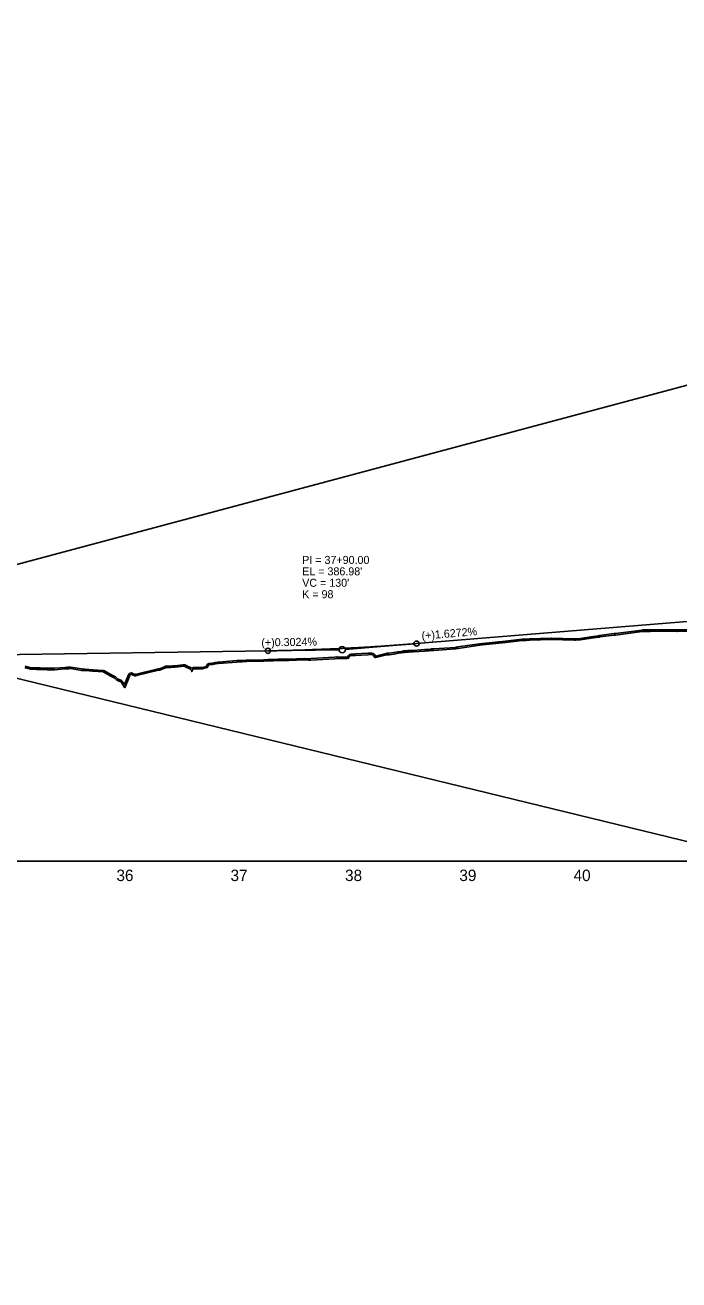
# Model space of a CAD drawing. Extents: x 1625686 to 1640492, y 1161393 to 1175642.
# Drawn here: x 1638424 to 1638996, y 1174544 to 1175642 of the extents above; entities that cross this region are included whole.
import ezdxf

# ---------------------------------------------------------------- set-up
doc = ezdxf.new("R2010")
doc.units = 0
for name, color, linetype in [('Exist Profile Cell', 7, 'Continuous'), ('Exist Vertical Profile Horizontal Axis Label Major', 7, 'Continuous'), ('Prop Vertical Profile Curve Label', 7, 'Continuous'), ('Prop Vertical Profile Grade', 7, 'Continuous'), ('Prop Vertical Profile Grade Label', 7, 'Continuous'), ('Prop VPI Label', 7, 'Continuous'), ('Scratch_Level_1', 7, 'Continuous'), ('Scratch_Level_3', 7, 'Continuous')]:
    doc.layers.add(name, color=color, linetype=linetype)

msp = doc.modelspace()

# ---------------------------------------------------------------- linework, layer by layer
at = {"layer": 'Exist Profile Cell'}
msp.add_line((1635911.8, 1174910.8), (1640378.1, 1174910.8), dxfattribs=at)
at = {"layer": 'Prop Vertical Profile Curve Label'}
for centre in [(1638636.8, 1175094.7), (1638766.8, 1175101)]:
    msp.add_circle(centre, 2.25, dxfattribs=at)
at = {"layer": 'Prop Vertical Profile Grade'}
for p, q in [((1638766.8, 1175101), (1639351.8, 1175148.6)), ((1638011.8, 1175085.3), (1638636.8, 1175094.7))]:
    msp.add_line(p, q, dxfattribs=at)
msp.add_spline([(1638636.8, 1175094.7), (1638639.4, 1175094.7), (1638642, 1175094.8), (1638644.6, 1175094.8), (1638647.2, 1175094.9), (1638649.8, 1175094.9), (1638652.4, 1175095), (1638655, 1175095.1), (1638657.6, 1175095.1), (1638660.2, 1175095.2), (1638662.8, 1175095.3), (1638665.4, 1175095.3), (1638668, 1175095.4), (1638670.6, 1175095.5), (1638673.2, 1175095.6), (1638675.8, 1175095.7), (1638678.4, 1175095.8), (1638681, 1175095.9), (1638683.6, 1175096), (1638686.2, 1175096.1), (1638688.8, 1175096.2), (1638691.4, 1175096.3), (1638694, 1175096.4), (1638696.6, 1175096.5), (1638699.2, 1175096.6), (1638701.8, 1175096.8), (1638704.4, 1175096.9), (1638707, 1175097), (1638709.6, 1175097.2), (1638712.2, 1175097.3), (1638714.8, 1175097.4), (1638717.4, 1175097.6), (1638720, 1175097.7), (1638722.6, 1175097.9), (1638725.2, 1175098), (1638727.8, 1175098.2), (1638730.4, 1175098.4), (1638733, 1175098.5), (1638735.6, 1175098.7), (1638738.2, 1175098.9), (1638740.8, 1175099), (1638743.4, 1175099.2), (1638746, 1175099.4), (1638748.6, 1175099.6), (1638751.2, 1175099.8), (1638753.8, 1175100), (1638756.4, 1175100.2), (1638759, 1175100.4), (1638761.6, 1175100.6), (1638764.2, 1175100.8), (1638766.8, 1175101)], degree=3, dxfattribs=at)
at = {"layer": 'Prop VPI Label'}
for p, q in [((1638636.8, 1175094.7), (1638699, 1175095.6)), ((1638766.8, 1175101), (1638704.5, 1175095.9))]:
    msp.add_line(p, q, dxfattribs=at)
msp.add_circle((1638701.8, 1175095.7), 2.75, dxfattribs=at)
at = {"layer": 'Scratch_Level_1'}
for p, q in [((1638866, 1175105.3), (1638884.6, 1175105.8)), ((1638939.5, 1175109.7), (1638940.2, 1175109.7)), ((1638939.7, 1175108.4), (1638940.3, 1175108.5)), ((1638964.4, 1175112.9), (1638965, 1175112.9)), ((1638964.4, 1175111.6), (1638965, 1175111.6)), ((1638965.1, 1175112.9), (1638970.2, 1175112.9)), ((1638965.1, 1175111.6), (1638970.2, 1175111.6)), ((1638995.4, 1175113.1), (1638996.3, 1175113.1)), ((1638995.5, 1175111.9), (1638996.3, 1175111.9)), ((1638754.8, 1175094.4), (1638755.8, 1175094.6)), ((1638756, 1175094.6), (1638757.9, 1175094.7)), ((1638759.7, 1175094.9), (1638761.7, 1175095)), ((1638802.9, 1175098.1), (1638821.9, 1175100.9)), ((1638803.1, 1175096.8), (1638822.1, 1175099.7)), ((1638821.9, 1175100.9), (1638824.5, 1175101.2)), ((1638822.1, 1175099.7), (1638824.6, 1175100)), ((1638836, 1175102.3), (1638838.8, 1175102.6)), ((1638836.1, 1175101), (1638838.9, 1175101.3)), ((1638866, 1175104.1), (1638884.7, 1175104.5)), ((1638590.7, 1175084.5), (1638593.4, 1175084.9)), ((1638590.9, 1175083.3), (1638593.6, 1175083.7)), ((1638593.6, 1175084.9), (1638609.5, 1175086.1)), ((1638593.7, 1175083.7), (1638609.6, 1175084.8)), ((1638609.5, 1175086.1), (1638612.8, 1175086.3)), ((1638609.6, 1175084.8), (1638612.8, 1175085)), ((1638724.2, 1175092.5), (1638727.8, 1175092.6)), ((1638724.3, 1175091.3), (1638727.8, 1175091.4)), ((1638755, 1175093.2), (1638756, 1175093.3)), ((1638756.1, 1175093.3), (1638758, 1175093.5)), ((1638759.7, 1175093.6), (1638761.7, 1175093.7)), ((1638424.2, 1175080), (1638424.8, 1175079.8)), ((1638424.4, 1175081.2), (1638425.1, 1175081.1)), ((1638424.9, 1175079.8), (1638426.1, 1175079.5)), ((1638425.1, 1175081), (1638426.4, 1175080.7)), ((1638437.3, 1175079.7), (1638438, 1175079.6)), ((1638437.3, 1175078.4), (1638438, 1175078.4)), ((1638450.2, 1175079.5), (1638459, 1175080.1)), ((1638450.3, 1175078.2), (1638459.1, 1175078.8)), ((1638462.4, 1175080.3), (1638463.6, 1175080.4)), ((1638462.5, 1175079.1), (1638463.7, 1175079.2)), ((1638476.9, 1175077.4), (1638483.5, 1175076.9)), ((1638477, 1175078.6), (1638483.6, 1175078.2)), ((1638483.5, 1175076.9), (1638492.7, 1175076.2)), ((1638483.6, 1175078.2), (1638492.8, 1175077.4)), ((1638547.7, 1175081.2), (1638548.1, 1175081.3)), ((1638547.7, 1175080), (1638548.2, 1175080)), ((1638560.8, 1175082.2), (1638562.5, 1175082.4)), ((1638560.9, 1175081), (1638562.6, 1175081.2)), ((1638562.6, 1175082.4), (1638563.5, 1175082.4)), ((1638562.7, 1175081.2), (1638563.5, 1175081.2)), ((1638569.6, 1175078), (1638570.1, 1175077))]:
    msp.add_line(p, q, dxfattribs=at)
for points in [[(1638859.5, 1175104.8), (1638862.5, 1175105), (1638865.8, 1175105.3)], [(1638884.7, 1175104.5), (1638904.7, 1175103.9), (1638905.8, 1175103.9), (1638910.3, 1175104.2), (1638919.6, 1175105.7)], [(1638884.8, 1175105.8), (1638904.7, 1175105.1), (1638905.7, 1175105.1), (1638910.2, 1175105.4), (1638919.3, 1175107)], [(1638919.4, 1175107), (1638925.7, 1175107.8), (1638926.2, 1175107.9)], [(1638919.6, 1175105.7), (1638925.9, 1175106.6), (1638926.5, 1175106.7)], [(1638926.4, 1175107.9), (1638927, 1175108), (1638939.4, 1175109.7)], [(1638926.5, 1175106.7), (1638927.1, 1175106.8), (1638939.6, 1175108.4)], [(1638940.3, 1175109.7), (1638940.8, 1175109.8), (1638964.1, 1175112.8)], [(1638940.3, 1175108.5), (1638940.9, 1175108.5), (1638964.3, 1175111.6)], [(1638970.2, 1175112.9), (1638970.6, 1175112.9), (1638971.1, 1175113)], [(1638970.2, 1175111.6), (1638970.7, 1175111.6), (1638971.3, 1175111.7)], [(1638971.5, 1175113), (1638994.5, 1175113), (1638995.2, 1175113.1)], [(1638971.5, 1175111.8), (1638994.6, 1175111.7), (1638995.3, 1175111.8)], [(1638996.3, 1175113.1), (1639007, 1175113.2), (1639009.1, 1175113.3), (1639023.6, 1175114.5), (1639029.2, 1175115)], [(1638996.3, 1175111.9), (1639007, 1175111.9), (1639009.2, 1175112), (1639023.8, 1175113.2), (1639029.4, 1175113.8)], [(1638750.7, 1175093.9), (1638753.3, 1175094.2), (1638753.5, 1175094.2), (1638754.8, 1175094.4)], [(1638758, 1175094.8), (1638758.6, 1175094.8), (1638759.6, 1175094.9)], [(1638761.8, 1175095), (1638764.2, 1175095), (1638774, 1175095.7)], [(1638761.8, 1175093.7), (1638764.3, 1175093.8), (1638774.1, 1175094.5)], [(1638774, 1175095.7), (1638777.4, 1175095.9), (1638779.3, 1175096.2)], [(1638774.1, 1175094.5), (1638777.5, 1175094.7), (1638779.5, 1175095)], [(1638779.6, 1175096.3), (1638781.8, 1175096.4), (1638800.8, 1175097.7), (1638801.7, 1175097.9), (1638802.9, 1175098)], [(1638779.7, 1175095), (1638781.9, 1175095.1), (1638800.9, 1175096.5), (1638801.9, 1175096.6), (1638803.1, 1175096.8)], [(1638824.7, 1175101.2), (1638827.3, 1175101.3), (1638835.9, 1175102.3)], [(1638824.7, 1175100), (1638827.4, 1175100.1), (1638836.1, 1175101)], [(1638838.8, 1175102.6), (1638841.9, 1175102.9), (1638859.3, 1175104.8)], [(1638838.9, 1175101.3), (1638842, 1175101.6), (1638859.5, 1175103.6)], [(1638859.5, 1175103.6), (1638862.6, 1175103.7), (1638865.9, 1175104.1)], [(1638585.2, 1175083.5), (1638588.2, 1175084), (1638590.6, 1175084.5)], [(1638612.9, 1175086.3), (1638614.3, 1175086.3), (1638617.9, 1175086.4)], [(1638612.9, 1175085), (1638614.4, 1175085.1), (1638618, 1175085.2)], [(1638618, 1175086.4), (1638633, 1175086.7), (1638636.9, 1175087.2)], [(1638618, 1175085.2), (1638633.1, 1175085.5), (1638637, 1175085.9)], [(1638637.1, 1175087.2), (1638641.5, 1175087.2), (1638645.4, 1175087.4)], [(1638637.1, 1175085.9), (1638641.5, 1175086), (1638645.4, 1175086.1)], [(1638645.5, 1175087.4), (1638650, 1175087.3), (1638655.1, 1175087.5), (1638668.4, 1175087.9)], [(1638645.5, 1175086.1), (1638650, 1175086.1), (1638655.2, 1175086.2), (1638668.4, 1175086.7)], [(1638668.5, 1175086.7), (1638672, 1175086.5), (1638672.9, 1175086.6)], [(1638668.6, 1175087.9), (1638672, 1175087.8), (1638672.9, 1175087.8)], [(1638672.9, 1175087.8), (1638674.3, 1175087.9), (1638695.1, 1175089.1), (1638696.8, 1175089.3)], [(1638673, 1175086.6), (1638674.4, 1175086.6), (1638695.2, 1175087.8), (1638697, 1175088)], [(1638697.2, 1175089.3), (1638699.1, 1175089.2), (1638705.9, 1175089.2), (1638706.5, 1175089.4), (1638707.2, 1175090.6)], [(1638697.2, 1175088), (1638699.1, 1175088), (1638706, 1175088), (1638707.3, 1175088.2), (1638708.3, 1175089.9)], [(1638709.2, 1175091.8), (1638713.3, 1175092), (1638724.2, 1175092.5)], [(1638709.3, 1175090.5), (1638713.3, 1175090.7), (1638724.2, 1175091.3)], [(1638728.9, 1175090.8), (1638730.2, 1175088.9), (1638731.1, 1175088.8), (1638740.5, 1175091.2)], [(1638729.9, 1175091.6), (1638730.9, 1175090.1), (1638731, 1175090.1), (1638740.2, 1175092.4)], [(1638740.9, 1175092.5), (1638742.9, 1175092.5), (1638747, 1175093.1), (1638750.5, 1175093.9)], [(1638740.9, 1175091.2), (1638743, 1175091.2), (1638747.2, 1175091.9), (1638750.7, 1175092.6)], [(1638750.9, 1175092.7), (1638753.4, 1175092.9), (1638753.7, 1175093), (1638755, 1175093.2)], [(1638758, 1175093.5), (1638758.6, 1175093.5), (1638759.7, 1175093.6)], [(1638426.2, 1175079.5), (1638429.2, 1175078.7), (1638429.4, 1175078.6)], [(1638426.5, 1175080.7), (1638429.4, 1175079.9), (1638429.5, 1175079.9)], [(1638429.5, 1175078.6), (1638430.2, 1175078.6), (1638431.5, 1175078.5), (1638432.7, 1175078.5), (1638434.6, 1175078.4)], [(1638429.6, 1175079.9), (1638430.3, 1175079.8), (1638431.5, 1175079.7), (1638432.7, 1175079.7), (1638434.6, 1175079.7)], [(1638434.6, 1175079.7), (1638435.2, 1175079.7), (1638437.3, 1175079.7)], [(1638434.6, 1175078.4), (1638435.2, 1175078.4), (1638437.2, 1175078.4)], [(1638438, 1175079.6), (1638440.4, 1175079.6), (1638441.9, 1175079.5)], [(1638438, 1175078.4), (1638440.4, 1175078.3), (1638441.9, 1175078.3)], [(1638441.9, 1175079.5), (1638443, 1175079.5), (1638444, 1175079.5), (1638445.5, 1175079.5), (1638446, 1175079.5)], [(1638441.9, 1175078.3), (1638443, 1175078.3), (1638443.9, 1175078.2), (1638445.5, 1175078.2), (1638446, 1175078.2)], [(1638446, 1175078.2), (1638448.1, 1175078.2), (1638449.3, 1175078.2), (1638450.3, 1175078.2)], [(1638446.1, 1175079.5), (1638448.1, 1175079.4), (1638449.3, 1175079.4), (1638450.2, 1175079.5)], [(1638459, 1175080.1), (1638461.6, 1175080.3), (1638462.4, 1175080.3)], [(1638459.1, 1175078.8), (1638461.7, 1175079), (1638462.5, 1175079.1)], [(1638464, 1175079.2), (1638473.8, 1175077.6), (1638476.9, 1175077.4)], [(1638464.2, 1175080.4), (1638473.9, 1175078.8), (1638477, 1175078.6)], [(1638493.2, 1175076), (1638498.7, 1175072.8), (1638502.8, 1175070.7)], [(1638493.8, 1175077.1), (1638499.3, 1175073.9), (1638503.4, 1175071.8)], [(1638508.6, 1175067), (1638511.4, 1175062.6), (1638511.6, 1175062.4), (1638515.9, 1175073.2)], [(1638509.6, 1175067.7), (1638511.3, 1175065.1), (1638514.8, 1175073.7)], [(1638517.6, 1175073.9), (1638520.4, 1175072.7), (1638520.9, 1175072.9)], [(1638518, 1175075.1), (1638520.5, 1175074.1), (1638520.6, 1175074.1)], [(1638520.8, 1175074.1), (1638521.7, 1175074.3), (1638540.8, 1175078.9)], [(1638521, 1175072.9), (1638521.9, 1175073), (1638541, 1175077.7)], [(1638541.3, 1175079), (1638541.8, 1175079), (1638544.3, 1175079.9), (1638546.8, 1175081)], [(1638541.3, 1175077.7), (1638542.1, 1175077.7), (1638544.8, 1175078.8), (1638547.3, 1175079.9)], [(1638548.2, 1175081.3), (1638549.9, 1175081.3), (1638550.6, 1175081.4), (1638552, 1175081.4)], [(1638548.2, 1175080), (1638550, 1175080.1), (1638550.7, 1175080.1), (1638552, 1175080.2)], [(1638552, 1175081.4), (1638553.2, 1175081.5), (1638555.1, 1175081.6), (1638555.7, 1175081.7), (1638557.6, 1175081.9), (1638558.2, 1175081.9), (1638560.1, 1175082.1), (1638560.7, 1175082.2)], [(1638552, 1175080.2), (1638553.3, 1175080.3), (1638555.2, 1175080.4), (1638555.8, 1175080.4), (1638557.7, 1175080.6), (1638558.3, 1175080.7), (1638560.3, 1175080.9), (1638560.9, 1175081)], [(1638564.2, 1175081.1), (1638565.2, 1175080.5), (1638569, 1175078.7)], [(1638564.8, 1175082.1), (1638565.8, 1175081.6), (1638569.6, 1175079.8)], [(1638570.1, 1175076.8), (1638570.2, 1175076.5), (1638570.7, 1175077.9)], [(1638571.8, 1175080), (1638579.3, 1175080.2), (1638582.9, 1175081.1), (1638583.3, 1175082.1)], [(1638571.8, 1175078.8), (1638579.4, 1175079), (1638583.7, 1175080), (1638584.4, 1175081.6)], [(1638585.4, 1175082.3), (1638588.5, 1175082.7), (1638590.8, 1175083.3)], [(1638503.1, 1175070.5), (1638504.5, 1175069.1), (1638508, 1175067.5)], [(1638504, 1175071.4), (1638505.3, 1175070.2), (1638508.6, 1175068.6)]]:
    msp.add_lwpolyline(points, dxfattribs=at)
for centre, radius, start, end in [((1638866, 1175102.8), 2.5, 91.4299, 95.8045), ((1638884.7, 1175103.3), 2.5, 88.0523, 91.4299), ((1638919.8, 1175104.5), 2.5, 97.6661, 99.6101), ((1638919.8, 1175104.5), 1.25, 97.6661, 99.6101), ((1638926.7, 1175105.5), 2.5, 97.2089, 100.5881), ((1638926.7, 1175105.5), 1.25, 97.2089, 100.5881), ((1638939.8, 1175107.2), 2.5, 95.0936, 97.527), ((1638939.8, 1175107.2), 1.25, 95.0936, 97.527), ((1638940.4, 1175107.2), 2.5, 92.8123, 95.0936), ((1638940.4, 1175107.2), 1.25, 92.8123, 95.0936), ((1638964.5, 1175110.4), 2.5, 91.7821, 97.5555), ((1638964.5, 1175110.4), 1.25, 91.7821, 97.5555), ((1638965.1, 1175110.4), 2.5, 89.9229, 91.7821), ((1638965.1, 1175110.4), 1.25, 89.9229, 91.7821), ((1638970.2, 1175110.4), 2.5, 88.5414, 89.9229), ((1638970.2, 1175110.4), 1.25, 88.5414, 89.9229), ((1638971.5, 1175110.5), 2.5, 89.9736, 101.357), ((1638971.5, 1175110.5), 1.25, 89.9736, 101.357), ((1638995.5, 1175110.6), 2.5, 91.0625, 97.4112), ((1638995.5, 1175110.6), 1.25, 91.0625, 97.4112), ((1638996.4, 1175110.6), 2.5, 90.3095, 91.0625), ((1638996.4, 1175110.6), 1.25, 90.3095, 91.0625), ((1638755.2, 1175091.9), 2.5, 99.2029, 99.2525), ((1638756.2, 1175092.1), 2.5, 94.9236, 99.2029), ((1638758.1, 1175092.3), 2.5, 92.4514, 94.9236), ((1638759.8, 1175092.4), 2.5, 92.9533, 95.5608), ((1638761.8, 1175092.5), 2.5, 90.7636, 92.9533), ((1638774.2, 1175093.2), 2.5, 93.7435, 93.9549), ((1638774.2, 1175093.2), 1.25, 93.7435, 93.9549), ((1638779.7, 1175093.8), 2.5, 92.1779, 99.2877), ((1638779.7, 1175093.8), 1.25, 92.1779, 99.2877), ((1638803.3, 1175095.6), 2.5, 98.5222, 99.1759), ((1638803.3, 1175095.6), 1.25, 98.5222, 99.1759), ((1638822.2, 1175098.4), 2.5, 96.8356, 98.5222), ((1638822.2, 1175098.4), 1.25, 96.8356, 98.5222), ((1638824.8, 1175098.7), 2.5, 92.4358, 96.8356), ((1638824.8, 1175098.7), 1.25, 92.4358, 96.8356), ((1638836.2, 1175099.8), 2.5, 95.6945, 96.3), ((1638836.2, 1175099.8), 1.25, 95.6945, 96.3), ((1638839, 1175100.1), 2.5, 95.667, 95.6945), ((1638839, 1175100.1), 1.25, 95.667, 95.6945), ((1638859.6, 1175102.3), 2.5, 93.0701, 96.2938), ((1638859.6, 1175102.3), 1.25, 93.0701, 96.2938), ((1638866, 1175102.8), 1.25, 91.4299, 95.8045), ((1638884.7, 1175103.3), 1.25, 88.0523, 91.4299), ((1638585.6, 1175081.1), 2.5, 97.8712, 155.793), ((1638591.1, 1175082), 2.5, 98.9095, 102.3318), ((1638593.8, 1175082.5), 2.5, 94.0736, 98.9095), ((1638593.8, 1175082.5), 1.25, 94.0736, 98.9095), ((1638609.7, 1175083.6), 2.5, 93.5017, 94.0736), ((1638609.7, 1175083.6), 1.25, 93.5017, 94.0736), ((1638612.9, 1175083.8), 2.5, 91.2796, 93.5017), ((1638612.9, 1175083.8), 1.25, 91.2796, 93.5017), ((1638618, 1175083.9), 2.5, 91.2444, 91.5746), ((1638618, 1175083.9), 1.25, 91.2444, 91.5746), ((1638637.2, 1175084.7), 2.5, 90.9678, 96.0955), ((1638637.2, 1175084.7), 1.25, 90.9678, 96.0955), ((1638645.5, 1175084.9), 2.5, 89.6465, 91.8664), ((1638645.5, 1175084.9), 1.25, 89.6465, 91.8664), ((1638668.5, 1175085.4), 2.5, 87.063, 92.0457), ((1638668.5, 1175085.4), 1.25, 87.063, 92.0457), ((1638673, 1175085.3), 2.5, 92.5257, 93.2675), ((1638673, 1175085.3), 1.25, 92.5257, 93.2675), ((1638697.1, 1175086.8), 2.5, 87.4665, 96.7534), ((1638697.1, 1175086.8), 1.25, 87.4665, 96.7534), ((1638709.4, 1175089.3), 2.5, 92.8949, 148.5708), ((1638709.4, 1175089.3), 1.25, 92.8949, 148.5708), ((1638724.3, 1175090.1), 2.5, 91.2357, 93.0935), ((1638724.3, 1175090.1), 1.25, 91.2357, 93.0935), ((1638727.9, 1175090.1), 2.5, 34.9361, 91.2357), ((1638727.9, 1175090.1), 1.25, 34.9361, 91.2357), ((1638740.8, 1175090), 2.5, 89.353, 104.0969), ((1638740.8, 1175090), 1.25, 89.353, 104.0969), ((1638751, 1175091.4), 2.5, 95.8894, 101.8206), ((1638751, 1175091.4), 1.25, 95.8894, 101.8206), ((1638755.2, 1175091.9), 1.25, 99.2029, 99.2525), ((1638756.2, 1175092.1), 1.25, 94.9236, 99.2029), ((1638758.1, 1175092.3), 1.25, 92.4514, 94.9236), ((1638759.8, 1175092.4), 1.25, 92.9533, 95.5608), ((1638761.8, 1175092.5), 1.25, 90.7636, 92.9533), ((1638423.9, 1175078.7), 2.5, 78.3717, 79.7394), ((1638424.6, 1175078.6), 1.25, 76.7061, 78.3717), ((1638424.6, 1175078.6), 2.5, 76.7061, 78.3717), ((1638425.8, 1175078.3), 1.25, 73.9503, 76.7061), ((1638425.8, 1175078.3), 2.5, 73.9503, 76.7061), ((1638429.3, 1175077.4), 1.25, 83.9447, 86.9867), ((1638429.3, 1175077.4), 2.5, 83.9447, 86.9867), ((1638434.6, 1175077.2), 2.5, 89.1999, 89.2854), ((1638434.6, 1175077.2), 1.25, 89.1999, 89.2854), ((1638437.2, 1175077.2), 1.25, 88.6132, 89.4231), ((1638437.2, 1175077.2), 2.5, 88.6132, 89.4231), ((1638438, 1175077.1), 2.5, 88.5278, 88.6132), ((1638438, 1175077.1), 1.25, 88.5278, 88.6132), ((1638441.8, 1175077), 2.5, 88.3664, 88.6336), ((1638441.8, 1175077), 1.25, 88.3664, 88.6336), ((1638446, 1175077), 2.5, 88.6524, 89.7492), ((1638446, 1175077), 1.25, 88.6524, 89.7492), ((1638450.4, 1175077), 2.5, 93.8158, 95.0189), ((1638450.4, 1175077), 1.25, 93.8158, 95.0189), ((1638459.2, 1175077.6), 2.5, 93.7115, 93.8158), ((1638459.2, 1175077.6), 1.25, 93.7115, 93.8158), ((1638462.6, 1175077.8), 2.5, 94.4196, 95.5104), ((1638462.6, 1175077.8), 1.25, 94.4196, 95.5104), ((1638463.8, 1175077.9), 2.5, 80.7399, 94.4196), ((1638463.8, 1175077.9), 1.25, 80.7399, 94.4196), ((1638476.8, 1175076.1), 1.25, 86.1568, 86.744), ((1638476.8, 1175076.1), 2.5, 86.1568, 86.744), ((1638483.4, 1175075.7), 1.25, 85.1932, 86.1568), ((1638483.4, 1175075.7), 2.5, 85.1932, 86.1568), ((1638492.6, 1175074.9), 1.25, 60.2283, 85.1932), ((1638492.6, 1175074.9), 2.5, 60.2283, 85.1932), ((1638517.1, 1175072.8), 2.5, 67.6989, 157.9426), ((1638517.1, 1175072.8), 1.25, 67.6989, 157.9426), ((1638521.3, 1175071.7), 2.5, 99.9586, 104.4775), ((1638521.3, 1175071.7), 1.25, 99.9586, 104.4775), ((1638541.3, 1175076.5), 2.5, 91.1484, 103.6241), ((1638541.3, 1175076.5), 1.25, 91.1484, 103.6241), ((1638547.8, 1175078.7), 2.5, 93.5392, 114.4462), ((1638547.8, 1175078.7), 1.25, 93.5392, 114.4462), ((1638548.3, 1175078.8), 2.5, 91.988, 93.5392), ((1638548.3, 1175078.8), 1.25, 91.988, 93.5392), ((1638552.1, 1175078.9), 2.5, 93.0224, 93.2987), ((1638552.1, 1175078.9), 1.25, 93.0224, 93.2987), ((1638561, 1175079.7), 2.5, 95.9909, 97.7233), ((1638561, 1175079.7), 1.25, 95.9909, 97.7233), ((1638562.8, 1175079.9), 2.5, 92.8332, 95.9909), ((1638562.8, 1175079.9), 1.25, 92.8332, 95.9909), ((1638563.6, 1175080), 2.5, 61.5289, 92.8332), ((1638563.6, 1175080), 1.25, 61.5289, 92.8332), ((1638568.5, 1175077.6), 1.25, 22.1434, 64.6259), ((1638568.5, 1175077.6), 2.5, 47.2664, 64.6259), ((1638568.9, 1175076.5), 1.25, 14.1628, 22.1434), ((1638571.9, 1175077.5), 2.5, 91.5164, 132.3903), ((1638571.9, 1175077.5), 1.25, 91.5164, 162.0818), ((1638585.6, 1175081.1), 1.25, 97.8712, 155.793), ((1638591.1, 1175082), 1.25, 98.9095, 102.3318), ((1638502.2, 1175069.6), 1.25, 46.0189, 62.5367), ((1638502.2, 1175069.6), 2.5, 46.0189, 62.5367), ((1638507.5, 1175066.4), 1.25, 32.2752, 64.9384), ((1638507.5, 1175066.4), 2.5, 32.2752, 64.9384)]:
    msp.add_arc(centre, radius, start, end, dxfattribs=at)
at = {"layer": 'Scratch_Level_3'}
for p, q in [((1636069.4, 1175642), (1640127.7, 1174654.2)), ((1636080.3, 1174544.5), (1640138.7, 1175631))]:
    msp.add_line(p, q, dxfattribs=at)
msp.add_lwpolyline([(1635911.8, 1174910.8), (1640049.2, 1174910.8), (1640049.2, 1175362.5)], dxfattribs=at)

# ---------------------------------------------------------------- texts
at = {"layer": 'Exist Vertical Profile Horizontal Axis Label Major'}
for s, p in [('36', (1638504.3, 1174893.3)), ('37', (1638604.1, 1174893.3)), ('38', (1638704.3, 1174893.3)), ('39', (1638804.3, 1174893.3)), ('40', (1638904.2, 1174893.3))]:
    msp.add_text(s, height=10, dxfattribs=at).set_placement(p)
at = {"layer": 'Prop Vertical Profile Curve Label'}
for s, p in [("VC = 130'", (1638666.8, 1175150.7)), ('K = 98', (1638666.8, 1175140.7))]:
    msp.add_text(s, height=7, dxfattribs=at).set_placement(p)
at = {"layer": 'Prop Vertical Profile Grade Label'}
for s, rotation, p in [('(+)0.3024%', 0.8663, (1638631.1, 1175098.5)), ('(+)1.6272%', 4.6514, (1638771.5, 1175104.4))]:
    msp.add_text(s, height=7, rotation=rotation, dxfattribs=at).set_placement(p)
at = {"layer": 'Prop VPI Label'}
for s, p in [('PI = 37+90.00', (1638666.8, 1175170.7)), ("EL = 386.98'", (1638666.8, 1175160.7))]:
    msp.add_text(s, height=7, dxfattribs=at).set_placement(p)

doc.saveas('drawing.dxf')
